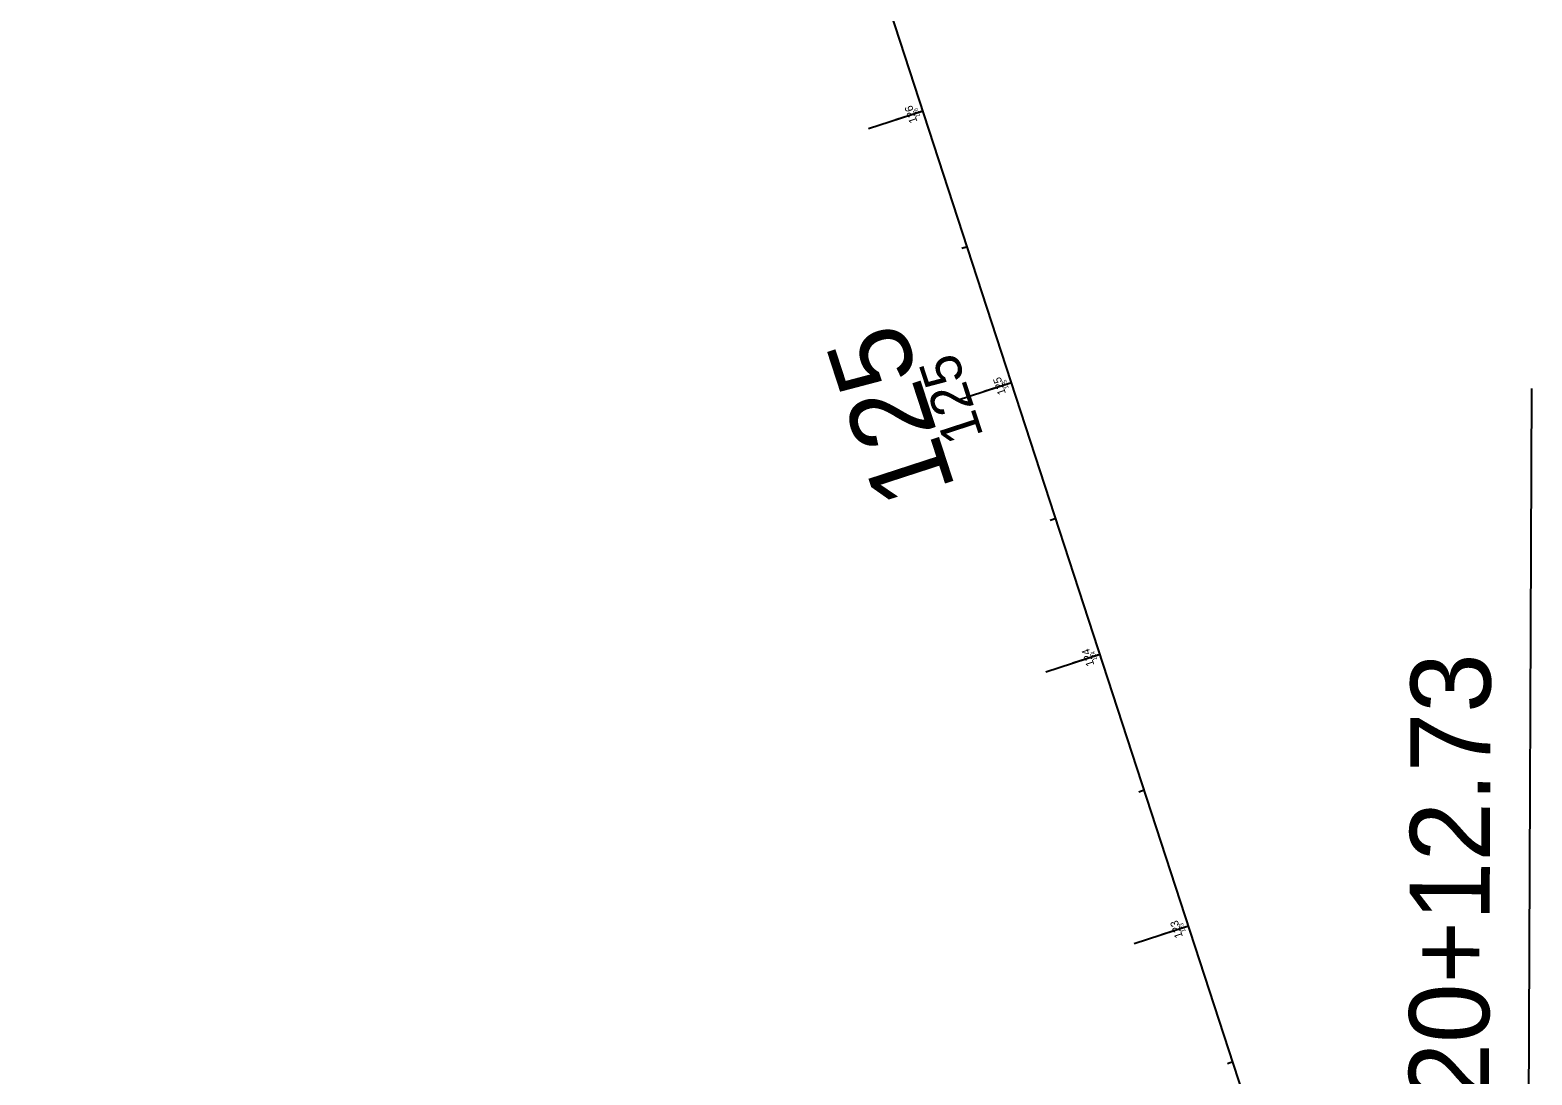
# Model space of a CAD drawing. Extents: x 1794716 to 1797874, y 325521 to 329174.
# Drawn here: x 1795747 to 1796272, y 327867 to 328233 of the extents above; entities that cross this region are included whole.
import ezdxf

# ---------------------------------------------------------------- set-up
doc = ezdxf.new("R2010")
doc.units = 0
for name, color, linetype in [('GE_P_CL_10', 7, 'Continuous'), ('GE_P_CL_100', 7, 'Continuous'), ('GE_P_CL_20', 7, 'Continuous'), ('GE_P_CL_200', 7, 'Continuous'), ('RW_X_CL_20', 7, 'Continuous')]:
    doc.layers.add(name, color=color, linetype=linetype)

msp = doc.modelspace()

# ---------------------------------------------------------------- linework, layer by layer
at = {"layer": 'GE_P_CL_10'}
for p, q in [((1796173.82, 327853.48), (1795747.03, 329164.17)), ((1796059.42, 328204.8), (1796058.47, 328204.49)), ((1796074.9, 328157.26), (1796073.95, 328156.95)), ((1796090.38, 328109.72), (1796089.43, 328109.41)), ((1796105.86, 328062.17), (1796104.91, 328061.86)), ((1796121.34, 328014.63), (1796120.39, 328014.32)), ((1796136.83, 327967.09), (1796135.87, 327966.78)), ((1796152.31, 327919.54), (1796151.36, 327919.23)), ((1796167.79, 327872), (1796166.84, 327871.69))]:
    msp.add_line(p, q, dxfattribs=at)
at = {"layer": 'GE_P_CL_100'}
for p, q in [((1796173.82, 327853.48), (1795747.03, 329164.17)), ((1796059.42, 328204.8), (1796049.91, 328201.71)), ((1796090.38, 328109.72), (1796080.87, 328106.62)), ((1796121.34, 328014.63), (1796111.84, 328011.53)), ((1796152.31, 327919.54), (1796142.8, 327916.45))]:
    msp.add_line(p, q, dxfattribs=at)
at = {"layer": 'GE_P_CL_20'}
for p, q in [((1796173.82, 327853.48), (1795747.03, 329164.17)), ((1796059.42, 328204.8), (1796057.52, 328204.18)), ((1796074.9, 328157.26), (1796073, 328156.64)), ((1796090.38, 328109.72), (1796088.48, 328109.1)), ((1796105.86, 328062.17), (1796103.96, 328061.55)), ((1796121.34, 328014.63), (1796119.44, 328014.01)), ((1796136.83, 327967.09), (1796134.92, 327966.47)), ((1796152.31, 327919.54), (1796150.4, 327918.92)), ((1796167.79, 327872), (1796165.89, 327871.38))]:
    msp.add_line(p, q, dxfattribs=at)
at = {"layer": 'GE_P_CL_200'}
for p, q in [((1796173.82, 327853.48), (1795747.03, 329164.17)), ((1796059.42, 328204.8), (1796040.4, 328198.61)), ((1796090.38, 328109.72), (1796071.37, 328103.52)), ((1796269.97, 327534.51), (1796272.45, 328107.72)), ((1796269.97, 327534.51), (1796272.45, 328107.72)), ((1796121.34, 328014.63), (1796102.33, 328008.44)), ((1796152.31, 327919.54), (1796133.29, 327913.35))]:
    msp.add_line(p, q, dxfattribs=at)
at = {"layer": 'RW_X_CL_20'}
msp.add_line((1796173.82, 327853.48), (1795747.03, 329164.17), dxfattribs=at)

# ---------------------------------------------------------------- texts
at = {"layer": 'GE_P_CL_10'}
for s, p in [('126', (1796058.45, 328202.94)), ('125', (1796089.41, 328107.86)), ('124', (1796120.37, 328012.79)), ('123', (1796151.33, 327917.69))]:
    msp.add_text(s, height=1.4, rotation=108.0361, dxfattribs=at).set_placement(p)
at = {"layer": 'GE_P_CL_100'}
msp.add_text('125', height=14, rotation=108.0361, dxfattribs=at).set_placement((1796080.64, 328091.19))
at = {"layer": 'GE_P_CL_20'}
for s, p in [('126', (1796057.48, 328201.09)), ('125', (1796088.43, 328106.01)), ('124', (1796119.39, 328010.96)), ('123', (1796150.36, 327915.83))]:
    msp.add_text(s, height=2.8, rotation=108.0361, dxfattribs=at).set_placement(p)
at = {"layer": 'GE_P_CL_200'}
for s, rotation, p in [('125', 108.0361, (1796070.9, 328072.66)), ('PI  Sta. 20+12.73', 89.7526, (1796256.79, 327724.57)), ('PI  Sta. 20+12.73', 89.7526, (1796256.79, 327724.57))]:
    msp.add_text(s, height=28, rotation=rotation, dxfattribs=at).set_placement(p)

doc.saveas('drawing.dxf')
